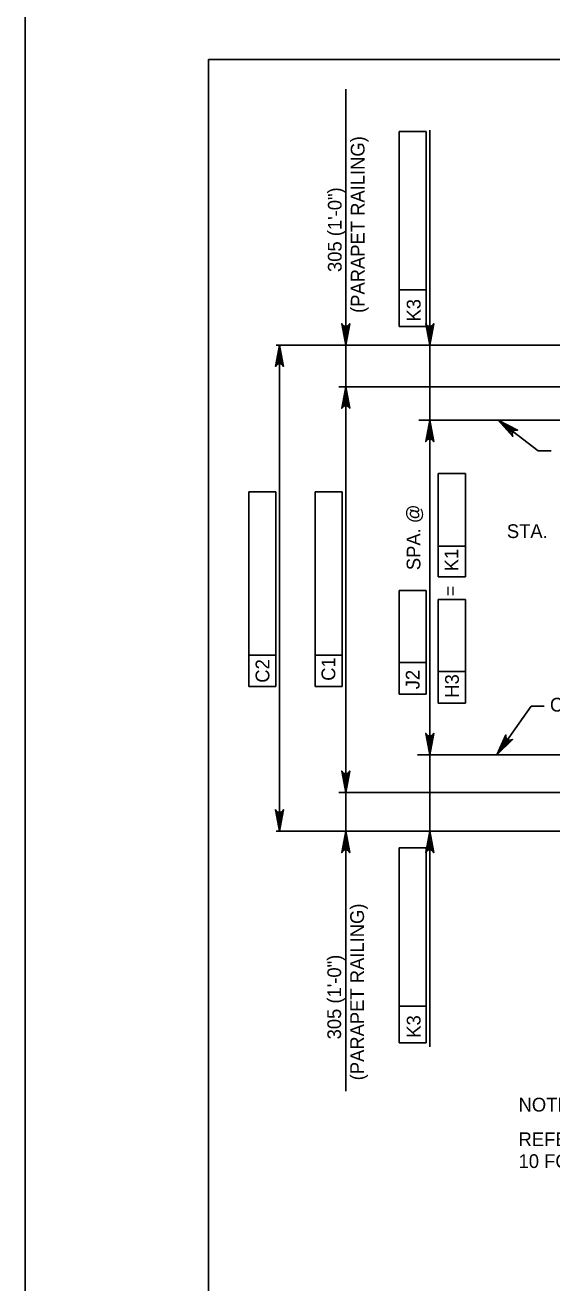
# Model space of a CAD drawing. Extents: x 638175 to 640495, y 294277 to 298435.
# Drawn here: x 638435.5 to 638550.4, y 294589.6 to 294864 of the extents above; entities that cross this region are included whole.
import ezdxf

# ---------------------------------------------------------------- set-up
doc = ezdxf.new("R2010")
doc.units = 0
for name, color, linetype in [('2', 7, 'Continuous'), ('4', 7, 'Continuous'), ('PLT-BNDY', 7, 'Continuous')]:
    doc.layers.add(name, color=color, linetype=linetype)

msp = doc.modelspace()

# ---------------------------------------------------------------- linework, layer by layer
at = {"layer": '2'}
for p, q in [((638475.46, 294292.46), (638475.46, 294856.46)), ((638475.46, 294856.46), (639261.46, 294856.46))]:
    msp.add_line(p, q, dxfattribs=at)
at = {"layer": '4'}
for p, q in [((638505.4, 294849.99), (638505.4, 294631.35)), ((638517.04, 294840.72), (638522.95, 294840.72)), ((638517.04, 294798.2), (638517.04, 294840.72)), ((638522.95, 294840.72), (638522.95, 294798.2)), ((638523.73, 294800.08), (638523.73, 294841.08)), ((638522.95, 294806.2), (638517.04, 294806.2)), ((638522.95, 294798.2), (638517.04, 294798.2)), ((638523.73, 294796.98), (638523.73, 294800.08)), ((638608.84, 294794.15), (638490.2, 294794.15)), ((638490.94, 294794.15), (638490.94, 294688.11)), ((638523.73, 294688.11), (638523.73, 294794.15)), ((638616.29, 294785.02), (638503.92, 294785.02)), ((638821.74, 294777.76), (638521.33, 294777.76)), ((638538.68, 294777.76), (638547.37, 294771.07)), ((638547.37, 294771.07), (638550.21, 294771.07)), ((638525.59, 294743.59), (638525.59, 294766.17)), ((638525.59, 294766.17), (638531.49, 294766.17)), ((638531.49, 294766.17), (638531.49, 294743.59)), ((638484.26, 294719.65), (638484.26, 294762.17)), ((638484.26, 294762.17), (638490.16, 294762.17)), ((638490.16, 294762.17), (638490.16, 294719.65)), ((638498.71, 294762.16), (638504.62, 294762.16)), ((638498.71, 294719.64), (638498.71, 294762.16)), ((638504.62, 294762.16), (638504.62, 294719.64)), ((638531.49, 294750.29), (638525.59, 294750.29)), ((638531.49, 294743.59), (638525.59, 294743.59)), ((638517.02, 294718), (638517.02, 294740.58)), ((638517.02, 294740.58), (638522.93, 294740.58)), ((638522.93, 294740.58), (638522.93, 294718)), ((638525.59, 294738.62), (638531.49, 294738.62)), ((638525.59, 294716.04), (638525.59, 294738.62)), ((638531.49, 294738.62), (638531.49, 294716.04)), ((638490.16, 294726.54), (638484.26, 294726.54)), ((638504.62, 294726.53), (638498.71, 294726.53)), ((638522.93, 294724.89), (638517.02, 294724.89)), ((638531.49, 294722.93), (638525.59, 294722.93)), ((638490.16, 294719.65), (638484.26, 294719.65)), ((638504.62, 294719.64), (638498.71, 294719.64)), ((638522.93, 294718), (638517.02, 294718)), ((638531.49, 294716.04), (638525.59, 294716.04)), ((638538.39, 294704.77), (638545.82, 294715.38)), ((638545.82, 294715.38), (638548.65, 294715.38)), ((638821.74, 294704.77), (638521.03, 294704.77)), ((638616.29, 294696.54), (638503.92, 294696.54)), ((638608.84, 294688.11), (638490.2, 294688.11)), ((638523.73, 294685.28), (638523.73, 294682.45)), ((638517.04, 294684.47), (638522.95, 294684.47)), ((638517.04, 294641.95), (638517.04, 294684.47)), ((638522.95, 294684.47), (638522.95, 294641.95)), ((638523.73, 294682.45), (638523.73, 294641.06)), ((638522.95, 294649.95), (638517.04, 294649.95)), ((638522.95, 294641.95), (638517.04, 294641.95))]:
    msp.add_line(p, q, dxfattribs=at)
for points in [[(638505.4, 294794.15), (638504.53, 294798.81), (638504.77, 294798.45), (638505.09, 294798.26), (638505.4, 294798.21), (638505.71, 294798.26), (638506.02, 294798.45), (638506.27, 294798.81), (638505.4, 294794.15), (638506.02, 294798.45), (638505.71, 294798.26), (638505.4, 294794.15), (638505.4, 294798.21), (638505.09, 294798.26), (638505.4, 294794.15), (638504.77, 294798.45)], [(638523.73, 294794.15), (638522.86, 294798.81), (638523.1, 294798.45), (638523.42, 294798.26), (638523.73, 294798.21), (638524.04, 294798.26), (638524.35, 294798.45), (638524.6, 294798.81), (638523.73, 294794.15), (638524.35, 294798.45), (638524.04, 294798.26), (638523.73, 294794.15), (638523.73, 294798.21), (638523.42, 294798.26), (638523.73, 294794.15), (638523.1, 294798.45)], [(638490.94, 294794.15), (638491.82, 294789.49), (638491.57, 294789.84), (638491.25, 294790.03), (638490.94, 294790.08), (638490.63, 294790.03), (638490.32, 294789.84), (638490.07, 294789.49), (638490.94, 294794.15), (638490.32, 294789.84), (638490.63, 294790.03), (638490.94, 294794.15), (638490.94, 294790.08), (638491.25, 294790.03), (638490.94, 294794.15), (638491.57, 294789.84)], [(638505.4, 294785.02), (638506.27, 294780.36), (638506.02, 294780.72), (638505.71, 294780.91), (638505.4, 294780.96), (638505.09, 294780.91), (638504.77, 294780.72), (638504.53, 294780.36), (638505.4, 294785.02), (638504.77, 294780.72), (638505.09, 294780.91), (638505.4, 294785.02), (638505.4, 294780.96), (638505.71, 294780.91), (638505.4, 294785.02), (638506.02, 294780.72)], [(638523.73, 294777.76), (638524.6, 294773.1), (638524.35, 294773.46), (638524.04, 294773.64), (638523.73, 294773.7), (638523.42, 294773.64), (638523.1, 294773.46), (638522.86, 294773.1), (638523.73, 294777.76), (638523.1, 294773.46), (638523.42, 294773.64), (638523.73, 294777.76), (638523.73, 294773.7), (638524.04, 294773.64), (638523.73, 294777.76), (638524.35, 294773.46)], [(638538.68, 294777.76), (638542.9, 294775.61), (638542.47, 294775.63), (638542.13, 294775.5), (638541.9, 294775.28), (638541.75, 294775), (638541.7, 294774.64), (638541.84, 294774.23), (638538.68, 294777.76), (638541.7, 294774.64), (638541.75, 294775), (638538.68, 294777.76), (638541.9, 294775.28), (638542.13, 294775.5), (638538.68, 294777.76), (638542.47, 294775.63)], [(638523.73, 294704.77), (638522.86, 294709.43), (638523.1, 294709.07), (638523.42, 294708.88), (638523.73, 294708.83), (638524.04, 294708.88), (638524.35, 294709.07), (638524.6, 294709.43), (638523.73, 294704.77), (638524.35, 294709.07), (638524.04, 294708.88), (638523.73, 294704.77), (638523.73, 294708.83), (638523.42, 294708.88), (638523.73, 294704.77), (638523.1, 294709.07)], [(638538.39, 294704.77), (638540.35, 294709.09), (638540.34, 294708.65), (638540.49, 294708.32), (638540.72, 294708.1), (638541.01, 294707.96), (638541.37, 294707.93), (638541.78, 294708.09), (638538.39, 294704.77), (638541.37, 294707.93), (638541.01, 294707.96), (638538.39, 294704.77), (638540.72, 294708.1), (638540.49, 294708.32), (638538.39, 294704.77), (638540.34, 294708.65)], [(638505.4, 294696.54), (638504.53, 294701.2), (638504.77, 294700.84), (638505.09, 294700.66), (638505.4, 294700.6), (638505.71, 294700.66), (638506.02, 294700.84), (638506.27, 294701.2), (638505.4, 294696.54), (638506.02, 294700.84), (638505.71, 294700.66), (638505.4, 294696.54), (638505.4, 294700.6), (638505.09, 294700.66), (638505.4, 294696.54), (638504.77, 294700.84)], [(638490.94, 294688.11), (638490.07, 294692.77), (638490.32, 294692.42), (638490.63, 294692.23), (638490.94, 294692.18), (638491.25, 294692.23), (638491.57, 294692.42), (638491.82, 294692.77), (638490.94, 294688.11), (638491.57, 294692.42), (638491.25, 294692.23), (638490.94, 294688.11), (638490.94, 294692.18), (638490.63, 294692.23), (638490.94, 294688.11), (638490.32, 294692.42)], [(638505.4, 294688.11), (638506.27, 294683.45), (638506.02, 294683.81), (638505.71, 294684), (638505.4, 294684.05), (638505.09, 294684), (638504.77, 294683.81), (638504.53, 294683.45), (638505.4, 294688.11), (638504.77, 294683.81), (638505.09, 294684), (638505.4, 294688.11), (638505.4, 294684.05), (638505.71, 294684), (638505.4, 294688.11), (638506.02, 294683.81)], [(638523.73, 294688.11), (638524.6, 294683.45), (638524.35, 294683.81), (638524.04, 294684), (638523.73, 294684.05), (638523.42, 294684), (638523.1, 294683.81), (638522.86, 294683.45), (638523.73, 294688.11), (638523.1, 294683.81), (638523.42, 294684), (638523.73, 294688.11), (638523.73, 294684.05), (638524.04, 294684), (638523.73, 294688.11), (638524.35, 294683.81)]]:
    msp.add_lwpolyline(points, dxfattribs=at)
for points in [[(638504.91, 294797.1), (638505.89, 294797.1), (638505.4, 294794.15)], [(638523.26, 294796.98), (638524.2, 294796.98), (638523.73, 294794.15)], [(638490.45, 294791.19), (638491.43, 294791.19), (638490.94, 294794.15)], [(638504.91, 294782.07), (638505.89, 294782.07), (638505.4, 294785.02)], [(638523.26, 294774.92), (638524.2, 294774.92), (638523.73, 294777.76)], [(638540.64, 294775.66), (638541.21, 294776.41), (638538.68, 294777.76)], [(638523.26, 294707.6), (638524.2, 294707.6), (638523.73, 294704.77)], [(638540.4, 294706.82), (638539.63, 294707.36), (638538.39, 294704.77)], [(638504.91, 294699.49), (638505.89, 294699.49), (638505.4, 294696.54)], [(638490.45, 294691.07), (638491.43, 294691.07), (638490.94, 294688.11)], [(638504.91, 294685.16), (638505.89, 294685.16), (638505.4, 294688.11)], [(638523.26, 294685.28), (638524.2, 294685.28), (638523.73, 294688.11)]]:
    msp.add_lwpolyline(points, close=True, dxfattribs=at)
at = {"layer": 'PLT-BNDY'}
msp.add_lwpolyline([(638435.46, 294871.46), (639276.46, 294871.46), (639276.46, 294277.46), (638435.46, 294277.46)], close=True, dxfattribs=at)

# ---------------------------------------------------------------- texts
at = {"layer": '4'}
for s, p in [('(PARAPET RAILING)', (638509.5, 294801.17)), ('305 (1\'-0")', (638504.5, 294810.1)), ('K3', (638521.71, 294799.3)), ('SPA. @', (638521.69, 294745.05)), ('K1', (638529.95, 294744.81)), ('=', (638529.7, 294739.34)), ('C2', (638488.73, 294720.5)), ('C1', (638503.11, 294720.91)), ('J2', (638521.5, 294719.06)), ('H3', (638530.07, 294717.22)), ('(PARAPET RAILING)', (638509.38, 294633.75)), ('305 (1\'-0")', (638504.38, 294642.68)), ('K3', (638521.71, 294643.04))]:
    msp.add_text(s, height=3, rotation=90, dxfattribs=at).set_placement(p)
for s, p in [('STA.', (638540.54, 294752.06)), ('C', (638549.94, 294714.2)), ('NOTE:', (638543.1, 294626.94)), ('REFER TO BLC-564M SHT. 9 OR', (638543.1, 294619.4)), ('10 FOR SUPERSTRUCTURE DETAILS', (638543.1, 294614.62))]:
    msp.add_text(s, height=3, dxfattribs=at).set_placement(p)

doc.saveas('drawing.dxf')
